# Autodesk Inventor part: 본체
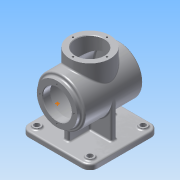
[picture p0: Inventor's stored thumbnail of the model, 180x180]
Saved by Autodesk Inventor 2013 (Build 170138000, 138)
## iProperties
Created: 2015-07
Part Number: 본체
Material: 알루미늄 6061
Document SubType Name: Modeling
Designer: ST3
Density: 2.71 g/cm^3
Mass: 1277.74 g
Surface Area: 1267.64 cm^2
Volume: 471.49 cm^3
Author: ST3
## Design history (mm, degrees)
sketch "스케치1"
  geometry: L1 (0, 0)-(128.399, 0); L2 (0, 27)-(0, 38); L3 (0, 38)-(7, 38); L4 (7, 38)-(7, 45); L5 (0, 27)-(14, 27); L6 (117, 45)-(117, 0); L7 (110, 40)-(110, 0); L8 (14, 27)-(14, 40); L9 (14, 40)-(110, 40); L10 (7, 45)-(117, 45)
  constraints: 20 end point, 5 perpendicular, 3 parallel, 2 point on line, 1 horizontal
  dimensions: "d0" = 54 diameter of L5 L1; "d3" = 76 diameter of L3 L1; "d8" = 80 diameter of L9 L1; "d9" = 14 distance between parallel lines of L8 L2; "d10" = 96 distance between parallel lines of L7 L8; "d11" = 7 distance between parallel lines of L6 L7; "d12" = 7 distance between parallel lines of L2 L4; "d13" = 90 diameter of L10 L1; "d14" = 0 distance from line of L1.start L2
revolve "회전1" sketch "스케치1" stored, may be unused: angle "d15" = 90 deg
fillet "모깎기1" dims "d16" = 3
chamfer "모따기1" distance "d17" = 1; stored, may be unused: second distance "d18" = 2, angle "d19" = 45 deg
fillet "모깎기2" dims "d20" = 3
fillet "모깎기3" dims "d21" = 3
node "작업 평면1"
sketch "스케치2"
  geometry: L1 (127, 65)-(-3, 65); L2 (-3, 65)-(-3, -65); L3 (-3, -65)-(127, -65); L4 (127, -65)-(127, 65); L5 (114, -45)-(114, 45) reference; L6 (10, 45)-(10, -45) reference; L7 (7, -42)-(7, 42) reference; 1 further point
  constraints: 8 end point, 2 parallel, 1 horizontal, 1 perpendicular
  dimensions: "d23" = 130 distance of L3.end L1.start; "d25" = 130 distance of L1.start L1.end; "d26" = 65 distance from line of point (0, 0) L1; "d27" = 10 distance between parallel lines of L7 L2
extrude "돌출1" join sketch "스케치2" distance "d28" = 10; taper "d29" = 0 deg
fillet "모깎기4" dims "d30" = 15
sketch "스케치3"
  geometry: C1 r 7.5 at (12, 50); C2 r 7.5 at (112, 50); C3 r 7.5 at (12, -50); C4 r 7.5 at (112, -50); A1 r 15 centre (112, -50) between (112, -65) and (127, -50) reference; A2 r 15 centre (112, 50) between (127, 50) and (112, 65) reference; A3 r 15 centre (12, 50) between (12, 65) and (-3, 50) reference; A4 r 15 centre (12, -50) between (-3, -50) and (12, -65) reference; 1 further point
  constraints: 4 centre point, 4 coincident
  dimensions: "d31" = 15 diameter of C1; "d33" = 15 diameter of C2; "d34" = 15 diameter of C4; "d35" = 15 diameter of C3
extrude "돌출2" join sketch "스케치3" distance "d36" = 3; taper "d37" = 0 deg
sketch "스케치4"
  geometry: C1 r 7.5 at (0, 0) reference; C2 r 5 at (0, 0); 1 further point
  constraints: 1 centre point, 1 coincident
  dimensions: "d38" = 10 diameter of C2
extrude "돌출3" cut sketch "스케치4" stored distance "d40" = 3; taper "d41" = 0 deg
node "작업 평면2"
fillet "모깎기5" dims "d42" = 3
fillet "모깎기6" dims "d43" = 3
sketch "스케치5"
  geometry: L1 (124, 50)-(124, -50) reference; L2 (0, 0)-(124, 0); L3 (62, 65.262)-(62, -65.262); L4 (127, -50)-(127, 50) reference; L5 (17, 5)-(57, 5); L6 (57, 5)-(57, 45); L7 (57, 45)-(67, 45); L8 (67, 45)-(67, 5); L9 (67, 5)-(107, 5); L10 (107, 5)-(107, -5); L11 (107, -5)-(67, -5); L12 (67, -5)-(67, -45); L13 (67, -45)-(57, -45); L14 (57, -45)-(57, -5); L15 (57, -5)-(17, -5); L16 (17, -5)-(17, 5)
  constraints: 28 end point, 7 perpendicular, 5 parallel, 3 collinear, 1 midpoint
  dimensions: "d44" = 65 distance between parallel lines of L4 L3; "d45" = 10 distance between parallel lines of L8 L6; "d46" = 10 distance between parallel lines of L15 L5; "d47" = 10 distance between parallel lines of L12 L14; "d48" = 10 distance between parallel lines of L9 L11; "d49" = 90 distance between parallel lines of L10 L16; "d50" = 90 distance between parallel lines of L13 L7; "d51" = 45 distance between parallel lines of L3 L16; "d52" = 45 distance between parallel lines of L2 L13; "d53" = 5 distance between parallel lines of L3 L6; "d54" = 5 distance between parallel lines of L2 L5
extrude "돌출4" join sketch "스케치5" stored distance "d55" = 3; taper "d56" = 0 deg
fillet "모깎기7" dims "d57" = 3
fillet "모깎기8" dims "d58" = 3
fillet "모깎기9" dims "d59" = 3
fillet "모깎기10" dims "d60" = 3
node "작업 평면4"
sketch "스케치7"
  geometry: L1 (7, -42)-(7, 42) reference; C1 r 38 at (62, 0); 1 further point
  constraints: 1 centre point
  dimensions: "d67" = 76 diameter of C1; "d69" = 0 vertical distance of point (0, 0) C1.centre; "d70" = 55 distance from line of L1 C1.centre
extrude "돌출5" join sketch "스케치7" stored distance "d71" = 3; taper "d72" = 0 deg
fillet "모깎기11" dims "d73" = 3
sketch "스케치8"
  geometry: C1 r 38 at (0, 0) reference; C2 r 27 at (0, 0); 1 further point
  constraints: 1 centre point, 1 coincident
  dimensions: "d74" = 54 diameter of C2
extrude "돌출6" cut sketch "스케치8" distance "d76" = 59.75; taper "d77" = 0 deg
chamfer "모따기2" distance "d78" = 1; stored, may be unused: second distance "d79" = 2, angle "d80" = 45 deg
sketch "스케치9" dims "d81" = 64
  geometry: L1 (0, 0)-(-62, 0); C1 r 28 at (0, 0) reference; C2 r 3.197 at (-32, 0)
  constraints: 2 end point, 1 centre point, 1 coincident, 1 horizontal, 1 horizontal alignment, 1 point on line, 2 other
hole "구멍1" sketch "스케치9" at (-32, 0) diameter "d83" = 3.242; stored, may be unused: countersink angle "d87" = 90 deg, drill point angle "d89" = 118 deg; dims "d84" = 8, "d85" = 4, "d86" = 2, "d88" = 10
sketch "스케치10" dims "d93" = 64
  geometry: L1 (0, 0)-(70.36, 0); C1 r 28 at (0, 0) reference; C2 r 3.938 at (32, 0)
  constraints: 2 end point, 1 centre point, 1 coincident, 1 horizontal, 1 horizontal alignment, 1 point on line, 2 other
hole "구멍2" sketch "스케치10" at (32, 0) diameter "d95" = 3.242; stored, may be unused: countersink angle "d99" = 90 deg, drill point angle "d101" = 118 deg; dims "d96" = 8, "d97" = 4, "d98" = 2, "d100" = 10
sketch "스케치11"
  geometry: L1 (-25, -10)-(-25, 10); L2 (-25, 10)-(25, 10); L3 (25, 10)-(25, -10); L4 (25, -10)-(-25, -10); C1 r 42 at (0, 0) reference
  constraints: 1 horizontal, 2 other
  dimensions: "d105" = 50 distance between parallel lines of L3 L1; "d107" = 20 distance between parallel lines of L2 L4; "d108" = 25 distance from line of C1.centre L1; "d109" = 10 distance from line of C1.centre L4
feature "엠보싱1" sketch "스케치11" dims "d20" = 3, "d110" = 0.5, "d111" = 0
fillet "모깎기12" dims "d112" = 3
fillet "모깎기13" dims "d113" = 3
node "솔리드1"
mirror "대칭1"
mirror "대칭2"
pattern_circular "원형 패턴1" dims angle "d91" = 360 deg
pattern_circular "원형 패턴2" dims angle "d103" = 360 deg
node "투영된 루프1"
other parameters: "d22" = -78, "d66" = 62
